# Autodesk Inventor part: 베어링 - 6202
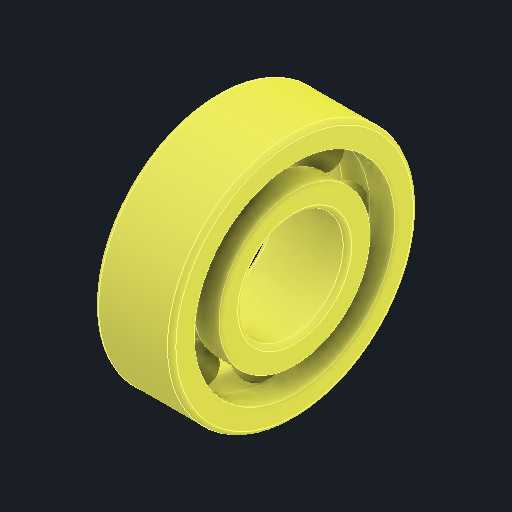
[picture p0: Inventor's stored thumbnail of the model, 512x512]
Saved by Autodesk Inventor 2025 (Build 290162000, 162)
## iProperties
Created: 2025-08
Part Number: 베어링 - 6202
Material: 강, 연강
Description: 깊은 그루브 볼 베어링
Document SubType Name: Modeling
Designer: infra15
Density: 7.86 g/cm^3
Appearance: 기본값
Author: jhkim
Sending System: Autodesk Inventor 2026
Preprocessor: ST-DEVELOPER v20.1
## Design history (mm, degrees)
feature "Solid1"
feature "Solid1:1"
feature "Solid1:2"
feature "Solid1:3"
feature "Solid1:4"
feature "Solid1:5"
feature "Solid1:6"
feature "Solid1:7"
feature "Solid1:8"
feature "Solid1:9"
node "솔리드1"
node "솔리드2"
node "솔리드3"
node "솔리드4"
node "솔리드5"
node "솔리드6"
node "솔리드7"
node "솔리드8"
node "솔리드9"
node "솔리드10"
